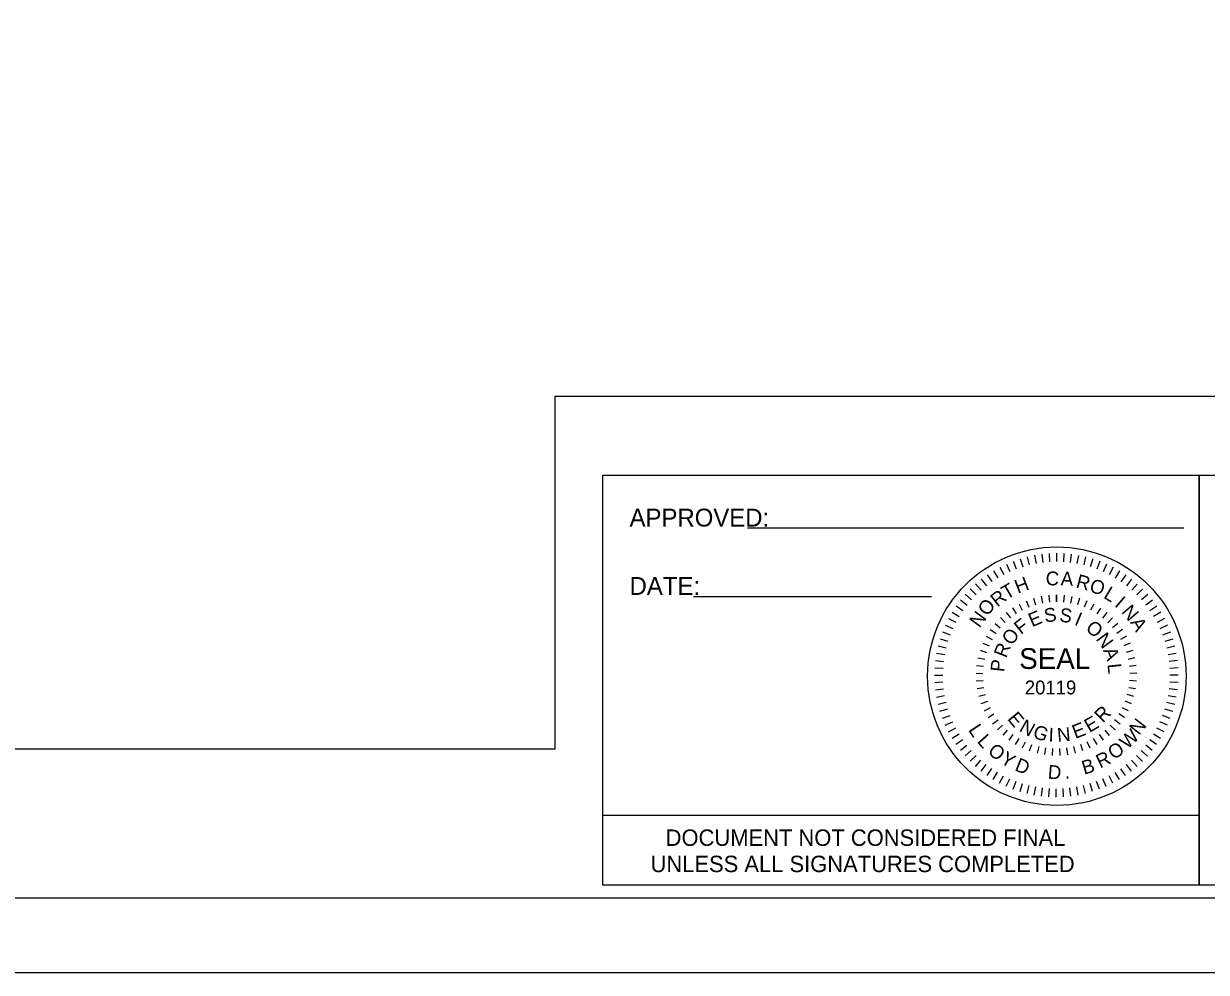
# Model space of a CAD drawing. Extents: x 766449 to 768137, y 650958 to 652521.
# Drawn here: x 767362.9 to 767759.5, y 651421.3 to 651739.5 of the extents above; entities that cross this region are included whole.
import ezdxf

# ---------------------------------------------------------------- set-up
doc = ezdxf.new("R2010")
doc.units = 0
for name, color, linetype in [('Default', 7, 'Continuous'), ('DEV BORDER CELL', 7, 'Continuous'), ('Scratch_Level_0', 7, 'Continuous'), ('Sheet Plot Border Outside CELL', 7, 'Continuous'), ('Sheet Sticker Exception Certification CELL', 7, 'Continuous')]:
    doc.layers.add(name, color=color, linetype=linetype)

msp = doc.modelspace()

# ---------------------------------------------------------------- linework, layer by layer
at = {"layer": 'Default'}
for p, q in [((767694.8, 651559.19), (767695.78, 651556.58)), ((767697.13, 651559.99), (767697.95, 651557.33)), ((767699.51, 651560.65), (767700.17, 651557.94)), ((767701.92, 651561.17), (767702.42, 651558.43)), ((767704.36, 651561.53), (767704.7, 651558.77)), ((767706.82, 651561.75), (767706.99, 651558.97)), ((767709.29, 651561.83), (767709.29, 651559.04)), ((767711.76, 651561.75), (767711.59, 651558.97)), ((767714.22, 651561.52), (767713.88, 651558.76)), ((767716.66, 651561.15), (767716.16, 651558.41)), ((767719.07, 651560.63), (767718.41, 651557.93)), ((767721.45, 651559.97), (767720.62, 651557.3)), ((767723.78, 651559.16), (767722.79, 651556.55)), ((767688.14, 651555.95), (767689.58, 651553.57)), ((767690.29, 651557.17), (767691.58, 651554.69)), ((767692.51, 651558.24), (767693.65, 651555.7)), ((767726.06, 651558.21), (767724.92, 651555.67)), ((767728.28, 651557.13), (767726.99, 651554.66)), ((767730.44, 651555.91), (767728.99, 651553.53)), ((767682.18, 651551.57), (767684.02, 651549.49)), ((767684.08, 651553.15), (767685.79, 651550.96)), ((767686.06, 651554.61), (767687.65, 651552.32)), ((767732.51, 651554.57), (767730.92, 651552.28)), ((767734.49, 651553.11), (767732.77, 651550.91)), ((767736.39, 651551.52), (767734.54, 651549.44)), ((767678.68, 651548.09), (767680.77, 651546.24)), ((767680.38, 651549.88), (767682.35, 651547.91)), ((767704.1, 651547.4), (767704.55, 651545.12)), ((767706.68, 651547.77), (767706.9, 651545.46)), ((767709.28, 651547.89), (767709.28, 651545.57)), ((767709.28, 651545.57), (767709.28, 651547.89)), ((767711.88, 651547.76), (767711.65, 651545.45)), ((767714.45, 651547.39), (767714.01, 651545.11)), ((767738.18, 651549.83), (767736.21, 651547.86)), ((767739.87, 651548.03), (767737.79, 651546.18)), ((767675.64, 651544.2), (767677.93, 651542.62)), ((767677.1, 651546.19), (767679.29, 651544.47)), ((767694.51, 651543.5), (767695.78, 651541.55)), ((767696.76, 651544.82), (767697.83, 651542.76)), ((767699.12, 651545.92), (767699.99, 651543.76)), ((767701.58, 651546.78), (767702.24, 651544.55)), ((767716.98, 651546.76), (767716.32, 651544.54)), ((767719.44, 651545.9), (767718.56, 651543.74)), ((767721.8, 651544.79), (767720.72, 651542.74)), ((767724.04, 651543.47), (767722.77, 651541.53)), ((767741.46, 651546.13), (767739.26, 651544.42)), ((767742.92, 651544.14), (767740.62, 651542.56)), ((767673.08, 651539.98), (767675.55, 651538.68)), ((767674.29, 651542.13), (767676.68, 651540.69)), ((767690.46, 651540.25), (767692.08, 651538.58)), ((767692.4, 651541.97), (767693.86, 651540.16)), ((767726.15, 651541.94), (767724.69, 651540.13)), ((767728.09, 651540.21), (767726.46, 651538.55)), ((767744.25, 651542.07), (767741.87, 651540.63)), ((767745.47, 651539.91), (767743, 651538.62)), ((767671.05, 651535.48), (767673.65, 651534.49)), ((767672, 651537.76), (767674.54, 651536.62)), ((767687.1, 651536.28), (767689.01, 651534.95)), ((767688.68, 651538.34), (767690.45, 651536.85)), ((767729.86, 651538.31), (767728.09, 651536.81)), ((767731.44, 651536.24), (767729.53, 651534.92)), ((767746.54, 651537.69), (767744, 651536.55)), ((767747.49, 651535.41), (767744.88, 651534.42)), ((767670.24, 651533.15), (767672.9, 651532.32)), ((767684.56, 651531.73), (767686.69, 651530.81)), ((767685.72, 651534.07), (767687.75, 651532.93)), ((767732.81, 651534.03), (767730.78, 651532.89)), ((767733.96, 651531.69), (767731.83, 651530.76)), ((767748.29, 651533.08), (767745.63, 651532.25)), ((767669.05, 651528.36), (767671.79, 651527.85)), ((767669.57, 651530.77), (767672.28, 651530.1)), ((767683.64, 651529.3), (767685.85, 651528.58)), ((767734.88, 651529.25), (767732.67, 651528.54)), ((767748.95, 651530.7), (767746.25, 651530.04)), ((767749.47, 651528.28), (767746.73, 651527.79)), ((767668.46, 651523.46), (767671.24, 651523.29)), ((767668.68, 651525.92), (767671.45, 651525.58)), ((767682.51, 651524.22), (767684.82, 651523.95)), ((767682.95, 651526.79), (767685.22, 651526.29)), ((767735.57, 651526.74), (767733.3, 651526.24)), ((767736, 651524.17), (767733.7, 651523.9)), ((767749.83, 651525.84), (767747.07, 651525.51)), ((767750.06, 651523.38), (767747.28, 651523.22)), ((767668.38, 651520.99), (767671.17, 651520.99)), ((767682.32, 651521.63), (767684.64, 651521.57)), ((767682.38, 651519.03), (767684.7, 651519.19)), ((767736.19, 651521.58), (767733.87, 651521.52)), ((767750.13, 651520.91), (767747.34, 651520.92)), ((767668.45, 651518.52), (767671.23, 651518.69)), ((767668.67, 651516.06), (767671.44, 651516.39)), ((767682.7, 651516.44), (767684.98, 651516.83)), ((767733.53, 651516.87), (767735.82, 651516.48)), ((767736.12, 651518.98), (767733.81, 651519.15)), ((767749.83, 651515.99), (767747.06, 651516.32)), ((767750.05, 651518.45), (767747.27, 651518.61)), ((767669.04, 651513.62), (767671.78, 651514.12)), ((767669.56, 651511.21), (767672.26, 651511.87)), ((767683.25, 651513.9), (767685.49, 651514.5)), ((767684.06, 651511.42), (767686.23, 651512.24)), ((767734.43, 651511.37), (767732.27, 651512.2)), ((767735.24, 651513.85), (767733, 651514.46)), ((767748.93, 651511.14), (767746.23, 651511.8)), ((767749.45, 651513.55), (767746.72, 651514.05)), ((767670.22, 651508.83), (767672.88, 651509.65)), ((767671.02, 651506.49), (767673.63, 651507.48)), ((767685.1, 651509.04), (767687.18, 651510.06)), ((767686.35, 651506.76), (767688.33, 651507.98)), ((767732.13, 651506.72), (767730.15, 651507.94)), ((767733.39, 651508.99), (767731.31, 651510.02)), ((767747.46, 651506.42), (767744.86, 651507.42)), ((767748.27, 651508.75), (767745.61, 651509.58)), ((767671.97, 651504.21), (767674.51, 651505.35)), ((767687.83, 651504.61), (767689.68, 651506.02)), ((767689.51, 651502.63), (767691.21, 651504.2)), ((767728.96, 651502.59), (767727.27, 651504.17)), ((767730.65, 651504.57), (767728.8, 651505.99)), ((767746.51, 651504.14), (767743.97, 651505.29)), ((767673.04, 651501.99), (767675.51, 651503.28)), ((767674.25, 651499.84), (767676.64, 651501.28)), ((767675.59, 651497.76), (767677.89, 651499.34)), ((767691.37, 651500.8), (767692.91, 651502.54)), ((767693.4, 651499.17), (767694.76, 651501.05)), ((767695.57, 651497.74), (767696.76, 651499.75)), ((767722.89, 651497.72), (767721.71, 651499.72)), ((767725.07, 651499.14), (767723.71, 651501.02)), ((767727.1, 651500.77), (767725.56, 651502.51)), ((767744.22, 651499.77), (767741.83, 651501.22)), ((767745.43, 651501.92), (767742.96, 651503.22)), ((767677.05, 651495.78), (767679.25, 651497.49)), ((767678.64, 651493.87), (767680.72, 651495.72)), ((767697.88, 651496.53), (767698.86, 651498.64)), ((767700.29, 651495.55), (767701.06, 651497.74)), ((767703.33, 651497.06), (767702.77, 651494.8)), ((767705.34, 651494.3), (767705.67, 651496.6)), ((767707.93, 651494.04), (767708.04, 651496.36)), ((767710.53, 651494.04), (767710.42, 651496.36)), ((767713.12, 651494.29), (767712.79, 651496.59)), ((767715.68, 651494.79), (767715.12, 651497.05)), ((767718.17, 651495.53), (767717.4, 651497.72)), ((767720.58, 651496.51), (767719.61, 651498.62)), ((767739.82, 651493.82), (767737.74, 651495.67)), ((767741.41, 651495.72), (767739.22, 651497.43)), ((767742.87, 651497.7), (767740.58, 651499.29)), ((767680.33, 651492.08), (767682.3, 651494.04)), ((767682.12, 651490.38), (767683.97, 651492.46)), ((767736.33, 651490.33), (767734.49, 651492.42)), ((767738.13, 651492.02), (767736.16, 651493.99)), ((767684.02, 651488.8), (767685.74, 651490.99)), ((767686, 651487.33), (767687.59, 651489.62)), ((767688.07, 651485.99), (767689.52, 651488.37)), ((767730.37, 651485.95), (767728.93, 651488.34)), ((767732.44, 651487.29), (767730.86, 651489.58)), ((767734.43, 651488.75), (767732.72, 651490.95)), ((767690.23, 651484.78), (767691.52, 651487.24)), ((767692.45, 651483.7), (767693.59, 651486.23)), ((767694.72, 651482.74), (767695.72, 651485.35)), ((767697.06, 651481.94), (767697.89, 651484.6)), ((767699.44, 651481.27), (767700.1, 651483.98)), ((767701.85, 651480.75), (767702.35, 651483.49)), ((767716.58, 651480.74), (767716.09, 651483.48)), ((767719, 651481.25), (767718.34, 651483.96)), ((767721.38, 651481.91), (767720.55, 651484.58)), ((767723.71, 651482.72), (767722.73, 651485.33)), ((767725.99, 651483.67), (767724.86, 651486.21)), ((767728.22, 651484.74), (767726.92, 651487.21)), ((767704.29, 651480.38), (767704.63, 651483.14)), ((767706.75, 651480.15), (767706.92, 651482.93)), ((767709.22, 651480.08), (767709.22, 651482.86)), ((767711.69, 651480.15), (767711.52, 651482.93)), ((767714.14, 651480.37), (767713.81, 651483.14))]:
    msp.add_line(p, q, dxfattribs=at)
at = {"layer": 'DEV BORDER CELL'}
for p, q in [((767605.7, 651570.37), (767752.04, 651570.37)), ((767757.19, 651564.55), (767757.19, 651450.55)), ((767587.58, 651547.29), (767667.37, 651547.29))]:
    msp.add_line(p, q, dxfattribs=at)
for points in [[(768112.34, 652496.28), (766612.34, 652496.28), (766612.34, 651446.28), (768112.34, 651446.28)], [(767557.15, 651588.05), (767757.19, 651588.05), (767757.19, 651450.55), (767557.15, 651450.55)], [(767757.19, 651588.05), (767871.19, 651588.05), (767871.19, 651450.55), (767757.19, 651450.55)]]:
    msp.add_lwpolyline(points, close=True, dxfattribs=at)
msp.add_circle((767709.41, 651520.61), 43.34, dxfattribs=at)
at = {"layer": 'Scratch_Level_0'}
msp.add_lwpolyline([(768062.34, 652446.28), (766662.34, 652446.28), (766662.34, 651496.28), (767541.19, 651496.28), (767541.19, 651614.55), (768062.34, 651614.55)], close=True, dxfattribs=at)
at = {"layer": 'Sheet Plot Border Outside CELL'}
msp.add_lwpolyline([(766449.34, 651421.28), (768137.34, 651421.28), (768137.34, 652521.28), (766449.34, 652521.28)], close=True, dxfattribs=at)
at = {"layer": 'Sheet Sticker Exception Certification CELL'}
for p, q in [((767557.15, 651450.55), (767557.15, 651474.05)), ((767557.15, 651474.05), (767757.19, 651474.05)), ((767757.19, 651474.04), (767757.19, 651450.54)), ((767757.19, 651450.55), (767557.15, 651450.55))]:
    msp.add_line(p, q, dxfattribs=at)

# ---------------------------------------------------------------- texts
at = {"layer": 'Default'}
for s, height, rotation, p in [('C', 4.64, 357.3039, (767705.57, 651551.19)), ('A', 4.64, 357.3039, (767710.64, 651551.1)), ('T', 4.64, 30.4466, (767692.6, 651546.2)), ('H', 4.64, 21.0146, (767696.33, 651548.22)), ('R', 4.64, 345.2946, (767715.56, 651550.41)), ('O', 4.64, 342.2378, (767720.05, 651549.07)), ('R', 4.64, 38.6075, (767689.47, 651543.61)), ('L', 4.64, 329.1015, (767724.77, 651547)), ('I', 4.64, 319.5261, (767728.51, 651544.3)), ('O', 4.64, 51.6643, (767686.11, 651540.49)), ('S', 4.64, 7.5951, (767705.44, 651538.6)), ('S', 4.64, 352.2989, (767710.08, 651538.98)), ('N', 4.64, 310.2316, (767730.83, 651542.11)), ('N', 4.64, 53.6237, (767683.44, 651536.57)), ('F', 4.64, 38.1876, (767697.37, 651534.39)), ('E', 4.64, 22.8914, (767701.08, 651537.01)), ('I', 4.64, 337.0026, (767715.01, 651537.97)), ('A', 4.64, 300.4641, (767733.89, 651538.68)), ('O', 4.64, 53.4838, (767694.28, 651530.65)), ('O', 4.64, 321.7064, (767718.75, 651536.16)), ('N', 4.64, 306.4101, (767722.32, 651533.05)), ('R', 4.64, 68.7801, (767692.44, 651526.48)), ('SEAL', 6.965, 359.947, (767696.78, 651523.05)), ('A', 4.64, 291.1139, (767724.86, 651529.25)), ('P', 4.64, 84.0763, (767691.73, 651521.88)), ('L', 4.64, 275.8176, (767726.36, 651524.66)), ('20119', 4.64, 359.947, (767698.67, 651514.52)), ('E', 4.64, 310.0171, (767692.61, 651506.23)), ('E', 4.64, 30.7408, (767720.36, 651501.54)), ('R', 4.64, 44.5119, (767724.78, 651504.77)), ('L', 4.64, 303.882, (767679.56, 651502.6)), ('N', 4.64, 330.8721, (767696.5, 651502.36)), ('G', 4.64, 339.6384, (767701.04, 651500.18)), ('I', 4.64, 357.7332, (767706.57, 651498.69)), ('N', 4.64, 5.3628, (767709.72, 651498.53)), ('E', 4.64, 20.7549, (767715.6, 651499.56)), ('N', 4.64, 52.154, (767737, 651500.56)), ('L', 4.64, 311.9538, (767682.43, 651498.62)), ('W', 4.64, 43.2714, (767733.1, 651495.9)), ('O', 4.64, 320.5966, (767685.95, 651494.96)), ('Y', 4.64, 329.2691, (767690.17, 651491.72)), ('O', 4.64, 34.3888, (767728.53, 651492.42)), ('D', 4.64, 338.2416, (767695, 651489.09)), ('B', 4.64, 16.5636, (767718.56, 651487.55)), ('R', 4.64, 25.5662, (767723.92, 651489.65)), ('D', 4.64, 356.0369, (767706.28, 651486.26)), ('.', 4.64, 3.7793, (767712.13, 651486.22))]:
    msp.add_text(s, height=height, rotation=rotation, dxfattribs=at).set_placement(p)
at = {"layer": 'DEV BORDER CELL'}
for s, p in [('APPROVED:  ', (767566.12, 651570.8)), ('DATE:  ', (767566.12, 651547.89))]:
    msp.add_text(s, height=6, dxfattribs=at).set_placement(p)
at = {"layer": 'Sheet Sticker Exception Certification CELL'}
for s, p in [('DOCUMENT NOT CONSIDERED FINAL', (767578.22, 651463.7)), ('UNLESS ALL SIGNATURES COMPLETED', (767573.15, 651454.9))]:
    msp.add_text(s, height=5.5, dxfattribs=at).set_placement(p)

doc.saveas('drawing.dxf')
